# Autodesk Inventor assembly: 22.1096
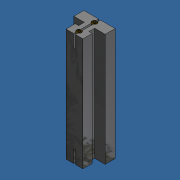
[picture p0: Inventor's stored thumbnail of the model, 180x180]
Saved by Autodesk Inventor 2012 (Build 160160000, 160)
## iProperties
Created: 2007-06
Part Number: 22.1096
Document SubType Name: Assembly
Designer: Andy Moles
Description: SLIDE RAIL LN-S
Vendor: S
Mass: 34.3995 g
Surface Area: 124.691 cm^2
Volume: 30.0098 cm^3
Density: 1.14628 g/cm^3
Author: Andy Moles
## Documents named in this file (5)
- C:\Andys Backup Data\ANDY'S INVENTOR\INVENTOR LIBRARIES\PARTS LIBRARY\COMPONENTS LG\22.1096 SLIDE RAIL LN-S.iam
- C:\Andys Backup Data\ANDY'S INVENTOR\INVENTOR LIBRARIES\PARTS LIBRARY\COMPONENTS LG\SUBCOMPONENTS\22.1096_1 SLIDE RAIL LN-S SLIDE BAR.ipt
- C:\Andys Backup Data\ANDY'S INVENTOR\INVENTOR LIBRARIES\PARTS LIBRARY\FASTENING ELEMENTS\SET SCREWS\21.1314 M4x8 SET SCREW POINTED.IPT
- C:\Andys Backup Data\ANDY'S INVENTOR\INVENTOR LIBRARIES\PARTS LIBRARY\FASTENING ELEMENTS\SCREWS CAP\21.1229 M4x12.ipt
- C:\Andys Backup Data\ANDY'S INVENTOR\INVENTOR LIBRARIES\PARTS LIBRARY\FASTENING ELEMENTS\THREADED INSERTS\21.9454_08 M4 X 8 HELICOIL.ipt
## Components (9 placed, 4 different names)
1. 22.1096_1 SLIDE RAIL LN-S SLIDE BAR:1 — Insert:3, Insert:4, Insert:5, Insert:6, Mate:1, Mate:2, Mate:3, Mate:4, Mate:5, Mate:6, Mate:7
2. 21.1314 M4X8 SET SCREW CONE POINT DIN 914:1 — Insert:3
3. 21.1314 M4X8 SET SCREW CONE POINT DIN 914:2 — Insert:4
4. 21.1314 M4X8 SET SCREW CONE POINT DIN 914:3 — Insert:5
5. 21.1314 M4X8 SET SCREW CONE POINT DIN 914:4 — Insert:6
6. 21.1229 SHCS M4X12 DIN 7984:1 — Mate:5, Flush:1, Mate:7
7. 21.1229 SHCS M4X12 DIN 7984:2 — Mate:6, Flush:1
8. 21.9454_08 M4 X 8 HELICOIL:1 — Mate:1, Mate:2
9. 21.9454_08 M4 X 8 HELICOIL:2 — Mate:3, Mate:4
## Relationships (12: Mate 7, Insert 4, Flush 1)
- Insert:3: 22.1096_1 SLIDE RAIL LN-S SLIDE BAR:1 ↔ 21.1314 M4X8 SET SCREW CONE POINT DIN 914:1
- Insert:4: 22.1096_1 SLIDE RAIL LN-S SLIDE BAR:1 ↔ 21.1314 M4X8 SET SCREW CONE POINT DIN 914:2
- Insert:5: 22.1096_1 SLIDE RAIL LN-S SLIDE BAR:1 ↔ 21.1314 M4X8 SET SCREW CONE POINT DIN 914:3
- Insert:6: 22.1096_1 SLIDE RAIL LN-S SLIDE BAR:1 ↔ 21.1314 M4X8 SET SCREW CONE POINT DIN 914:4
- Mate:1: 22.1096_1 SLIDE RAIL LN-S SLIDE BAR:1 ↔ 21.9454_08 M4 X 8 HELICOIL:1
- Mate:2: 22.1096_1 SLIDE RAIL LN-S SLIDE BAR:1 ↔ 21.9454_08 M4 X 8 HELICOIL:1
- Mate:3: 22.1096_1 SLIDE RAIL LN-S SLIDE BAR:1 ↔ 21.9454_08 M4 X 8 HELICOIL:2
- Mate:4: 22.1096_1 SLIDE RAIL LN-S SLIDE BAR:1 ↔ 21.9454_08 M4 X 8 HELICOIL:2
- Mate:5: 22.1096_1 SLIDE RAIL LN-S SLIDE BAR:1 ↔ 21.1229 SHCS M4X12 DIN 7984:1
- Mate:6: 22.1096_1 SLIDE RAIL LN-S SLIDE BAR:1 ↔ 21.1229 SHCS M4X12 DIN 7984:2
- Flush:1: 21.1229 SHCS M4X12 DIN 7984:1 ↔ 21.1229 SHCS M4X12 DIN 7984:2
- Mate:7: 22.1096_1 SLIDE RAIL LN-S SLIDE BAR:1 ↔ 21.1229 SHCS M4X12 DIN 7984:1
